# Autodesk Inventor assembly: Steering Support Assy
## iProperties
Length Units: 11269
Angle Units: 11279
Time Units: 11290
Mass Units: 11283
Shininess: 3
Angle Display Precision: 2
Document Length Units: 11269
Document Angle Units: 11279
Document Time Units: 11290
Document Mass Units: 11283
Document Length Units Precision: 3
Document Angle Units Precision: 2
Created: 2001-08
Part Number: Steering Support Assy
Document SubType Name: Assembly
Designer: Martin Budgell
Density: 0.0
Volumn: 0.0
Area: 0.0
PropertySet Name: Model Information
Control State: 0
Master: False
Checked Out: False
Author: Martin Budgell
